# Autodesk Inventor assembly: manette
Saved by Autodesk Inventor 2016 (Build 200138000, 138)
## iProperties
Created: 2014-02
Part Number: manette
Material: Générique
Document SubType Name: Assembly
Designer: Bruno
Author: Bruno
Sending System: SolidWorks 2013
Last Author: christophe
Last Saved: 2014-02-15
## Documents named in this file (2)
- D:\Cours\Systèmes SI\Robot Haptique\Documentations_pedagogique\Modèle solidworks\Réel\manette.iam
- D:\Cours\Systèmes SI\Robot Haptique\Documentations_pedagogique\Modèle solidworks\Réel\manette1.ipt
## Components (1 placed, 1 different names)
1. manette1:1
